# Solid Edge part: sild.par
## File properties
Author: Mac
Template: Normal.par
Last saved by: Mac
Revision: 7
Application: Solid Edge
Material: Epoxy, cast rigid
Face Style: White
Fill Style: ANSI34(Plastic)
Virtual Style: Shiny resin yellow
Coef. of Thermal Exp: 5.9e-05
Thermal Conductivity: 2.1
Specific Heat: 0.0
Modulus of Elasticity: 3102640650.0
Poission's Ratio: 0.37
Yield Stress: 65500191.5
Ultimate Stress: 0.0
Elongation: 0.0
Density: 1300,000 kg/m^3
Accuracy: 0,990
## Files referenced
..\..\paat abi3\Asm12.asm
BC:\Documents and Settings\Mac\Desktop\paat\Abi\paat abi3\Asm12.asm
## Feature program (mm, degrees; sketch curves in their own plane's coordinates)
sketch for "unnamed Protrusion 1" plane through (11.1308, -2.2248, 1) normal (0, 0, 1) x-axis (0, 1, 0)
extrude "unnamed Protrusion 1" add finite 1 along -normal
thinwall "Thinwall_1"  Thickness = 0.2 mm
fillet "Round_1" radius 0.2
body pattern "unnamed BodyPattern 1"
pattern "unnamed Pattern 1"
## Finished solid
Body 1: solid body, 39 faces, 103 edges, 67 vertices.
  Faces by surface: plane 13, cylinder 12, offset 6, swept 6, blend 2
  Edges by curve: line 48, intersection 21, circle 16, spline 10, curve on surface 6, ellipse 2
Bounding box of the edges (mm; curved faces can reach further): 47.417 x 69.544 x 1.000, from (-20.0001, -55.8524, 0) to (27.4171, 13.6916, 1).
Cylindrical faces by radius (mm): R0.2 x4, R257.4966 x2, R257.6966 x2, R1331.7636 x2, R1331.9636 x2
Planar faces by outward normal: +x 1, +z 1, -x 1, -z 2, oblique 8
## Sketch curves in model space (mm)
spline (7.8222, 12.217, 1) -> (5.5109, 11.0916, 1) -> (4.2505, 8.8391, 1)
arc centre (256.3417, -43.6445, 1) radius 257.4966 from (3.0903, 2.9196, 1) through (3.653, 5.8827, 1) to (4.2505, 8.8391, 1)
spline (3.0903, 2.9196, 1) -> (1.2374, -8.7915, 1) -> (0, -20.5804, 1)
line (0, -20.5804, 1) -> (0, -21.0804, 1)
line (-20, -21.0804, 1) -> (0, -21.0804, 1)
spline (-20, -21.0804, 1) -> (-16.4566, 7.2877, 1) -> (7.7968, 13.2167, 1)
line (7.7968, 13.2167, 1) -> (26.4738, 13.6916, 1)
line (26.4738, 13.6916, 1) -> (27.4171, 12.7483, 1)
arc centre (53.7137, -1318.7557, 1) radius 1331.7636 from (27.4171, 12.7483, 1) through (17.6187, 12.5187, 1) to (7.8222, 12.217, 1)
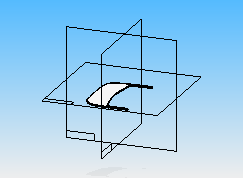
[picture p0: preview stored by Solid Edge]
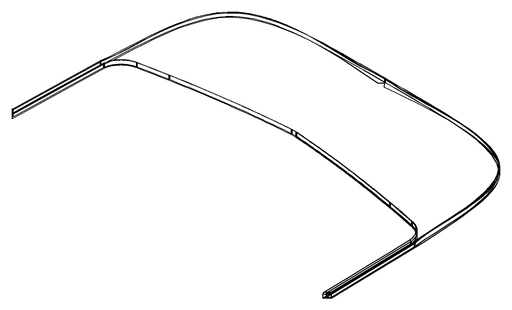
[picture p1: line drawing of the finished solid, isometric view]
